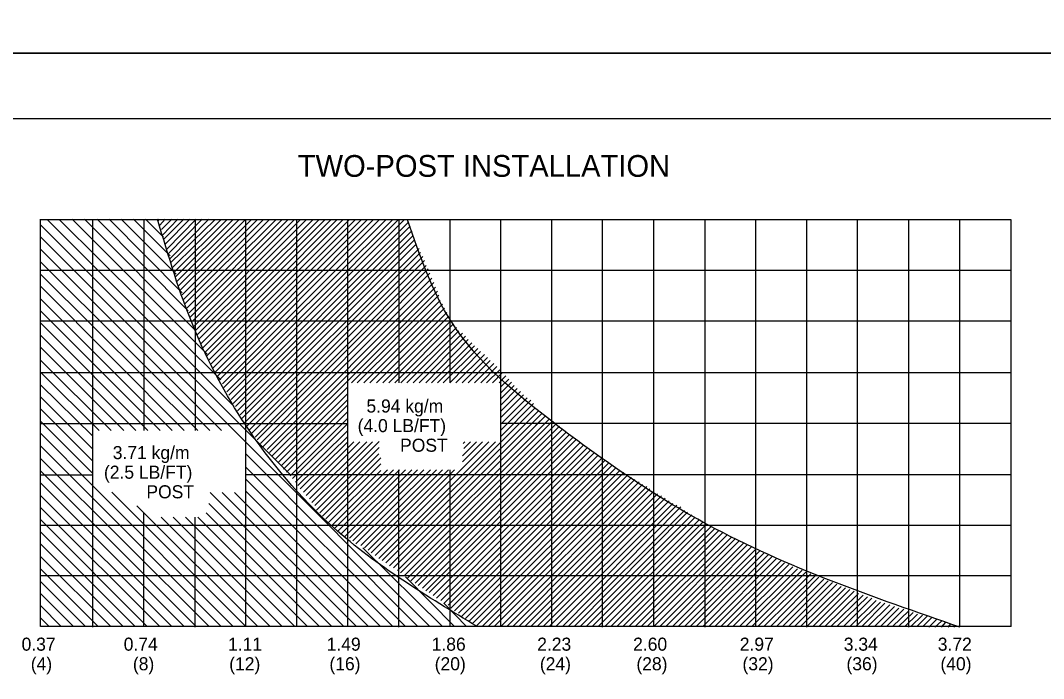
# Model space of a CAD drawing. Extents: x 644358 to 648627, y 294594 to 295782.
# Drawn here: x 645519 to 645753.8, y 295044.1 to 295195.1 of the extents above; entities that cross this region are included whole.
import ezdxf

# ---------------------------------------------------------------- set-up
doc = ezdxf.new("R2010")
doc.units = 0
for name, color, linetype in [('1', 7, 'Continuous'), ('10', 7, 'Continuous'), ('2', 7, 'Continuous'), ('4', 7, 'Continuous'), ('PLT-BNDY', 7, 'Continuous')]:
    doc.layers.add(name, color=color, linetype=linetype)

msp = doc.modelspace()

# ---------------------------------------------------------------- linework, layer by layer
at = {"layer": '1'}
msp.add_line((645239.31, 295172.63), (646025.31, 295172.63), dxfattribs=at)
at = {"layer": '10'}
for p, q in [((645567.96, 295106.63), (645525.21, 295149.38)), ((645564.96, 295112.63), (645527.96, 295149.38)), ((645561.84, 295118.5), (645530.84, 295149.5)), ((645558.84, 295124.25), (645533.71, 295149.5)), ((645557.46, 295128.5), (645536.59, 295149.5)), ((645556.09, 295132.63), (645539.34, 295149.5)), ((645554.71, 295136.88), (645542.09, 295149.5)), ((645553.34, 295141.13), (645544.96, 295149.5)), ((645551.84, 295145.38), (645547.71, 295149.5)), ((645550.59, 295149.13), (645550.84, 295149.5)), ((645550.96, 295148.13), (645552.21, 295149.5)), ((645551.34, 295147.13), (645553.71, 295149.5)), ((645551.59, 295145.88), (645555.09, 295149.5)), ((645551.84, 295144.88), (645556.46, 295149.5)), ((645552.21, 295143.75), (645557.84, 295149.5)), ((645552.59, 295142.63), (645559.34, 295149.5)), ((645552.96, 295141.63), (645560.71, 295149.5)), ((645553.34, 295140.5), (645562.21, 295149.5)), ((645553.46, 295139.5), (645563.59, 295149.38)), ((645553.84, 295138.38), (645564.96, 295149.38)), ((645554.21, 295137.25), (645566.34, 295149.38)), ((645554.59, 295136.25), (645567.71, 295149.38)), ((645554.84, 295135.13), (645569.09, 295149.38)), ((645555.21, 295134.13), (645570.59, 295149.38)), ((645555.59, 295133.13), (645571.96, 295149.38)), ((645556.09, 295132.13), (645573.34, 295149.38)), ((645556.34, 295131), (645574.71, 295149.38)), ((645556.84, 295130.13), (645576.09, 295149.38)), ((645557.21, 295129.13), (645577.59, 295149.38)), ((645557.71, 295128), (645578.96, 295149.38)), ((645557.96, 295127), (645580.34, 295149.38)), ((645558.46, 295126.13), (645581.84, 295149.38)), ((645558.84, 295125), (645583.21, 295149.38)), ((645559.21, 295124), (645584.59, 295149.38)), ((645559.59, 295123), (645586.09, 295149.38)), ((645559.96, 295122), (645587.46, 295149.38)), ((645560.46, 295121), (645588.84, 295149.38)), ((645560.84, 295120), (645590.21, 295149.38)), ((645561.21, 295118.88), (645591.59, 295149.38)), ((645561.59, 295118), (645592.96, 295149.38)), ((645562.21, 295117.13), (645594.46, 295149.38)), ((645562.59, 295116.13), (645595.84, 295149.38)), ((645563.21, 295115.38), (645597.21, 295149.38)), ((645563.71, 295114.38), (645598.59, 295149.38)), ((645564.21, 295113.5), (645599.96, 295149.38)), ((645564.71, 295112.63), (645601.34, 295149.38)), ((645565.34, 295111.75), (645602.84, 295149.38)), ((645565.71, 295110.88), (645604.34, 295149.38)), ((645566.34, 295109.88), (645605.71, 295149.38)), ((645566.84, 295109.13), (645607.09, 295149.38)), ((645567.34, 295108.13), (645608.09, 295148.88)), ((645580.96, 295090.88), (645523.59, 295148.25)), ((645567.84, 295107.25), (645608.46, 295147.88)), ((645568.34, 295106.5), (645608.84, 295146.88)), ((645570.71, 295098.31), (645523.59, 295145.5)), ((645568.84, 295105.5), (645609.09, 295145.75)), ((645569.46, 295104.63), (645609.46, 295144.75)), ((645569.84, 295103.75), (645609.84, 295143.75)), ((645565.11, 295100.99), (645523.59, 295142.63)), ((645570.46, 295102.88), (645610.51, 295142.8)), ((645570.96, 295102), (645610.81, 295141.85)), ((645562.46, 295100.99), (645523.59, 295139.75)), ((645571.46, 295101.13), (645611.33, 295140.99)), ((645572.09, 295100.38), (645611.71, 295140)), ((645572.84, 295099.5), (645612.13, 295138.92)), ((645559.7, 295100.99), (645523.59, 295136.88)), ((645573.34, 295098.88), (645612.56, 295138.1)), ((645574.09, 295098), (645612.97, 295137.14)), ((645574.59, 295097.25), (645613.42, 295135.96)), ((645575.6, 295096.64), (645613.83, 295135)), ((645556.6, 295100.99), (645523.59, 295134.13)), ((645594.09, 295113.82), (645614.25, 295133.91)), ((645594.09, 295112.44), (645614.72, 295133)), ((645594.98, 295111.96), (645615.03, 295132.08)), ((645553.85, 295100.99), (645523.59, 295131.25)), ((645596.3, 295111.96), (645615.34, 295130.88)), ((645597.79, 295111.96), (645615.84, 295130)), ((645551.1, 295100.99), (645523.59, 295128.5)), ((645599.17, 295111.96), (645616.34, 295129.13)), ((645600.67, 295111.96), (645616.84, 295128.13)), ((645602.15, 295111.96), (645617.34, 295127.25)), ((645548.23, 295100.99), (645523.59, 295125.75)), ((645603.54, 295111.96), (645617.84, 295126.25)), ((645604.9, 295111.96), (645618.34, 295125.5)), ((645545.47, 295100.99), (645523.59, 295122.88)), ((645606.31, 295111.96), (645619.09, 295124.63)), ((645607.67, 295111.96), (645619.59, 295123.88)), ((645609.15, 295111.96), (645620.43, 295123.35)), ((645610.52, 295111.96), (645621.09, 295122.64)), ((645612, 295111.96), (645621.72, 295121.89)), ((645613.32, 295111.96), (645622.6, 295121.13)), ((645614.67, 295111.96), (645623.19, 295120.48)), ((645542.72, 295100.99), (645523.59, 295120.13)), ((645616.04, 295111.96), (645623.93, 295119.85)), ((645617.51, 295111.96), (645624.59, 295119.14)), ((645618.92, 295111.96), (645625.45, 295118.49)), ((645539.83, 295100.99), (645523.59, 295117.13)), ((645620.33, 295111.96), (645626.21, 295117.74)), ((645621.75, 295111.96), (645626.79, 295117.1)), ((645623.17, 295111.96), (645627.61, 295116.4)), ((645624.61, 295111.96), (645628.28, 295115.72)), ((645537.08, 295100.99), (645523.59, 295114.38)), ((645576.17, 295095.96), (645594.09, 295113.82)), ((645625.98, 295111.96), (645629.03, 295114.92)), ((645627.35, 295111.96), (645629.63, 295114.32)), ((645628.83, 295111.96), (645630.35, 295113.54)), ((645535.59, 295099.71), (645523.59, 295111.5)), ((645576.8, 295095.22), (645594.09, 295112.44)), ((645577.52, 295094.44), (645594.09, 295111.06)), ((645629.21, 295111.05), (645631.04, 295112.8)), ((645629.21, 295109.63), (645631.71, 295112.13)), ((645629.21, 295108.25), (645632.32, 295111.35)), ((645535.59, 295096.75), (645523.59, 295108.75)), ((645578.05, 295093.58), (645594.09, 295109.48)), ((645629.21, 295106.83), (645633.02, 295110.64)), ((645629.21, 295105.42), (645633.73, 295109.94)), ((645629.21, 295104), (645634.44, 295109.23)), ((645629.21, 295102.5), (645635.24, 295108.53)), ((645578.85, 295092.89), (645594.09, 295108.13)), ((645579.39, 295092.18), (645594.09, 295106.88)), ((645602, 295071.17), (645637.02, 295106.18)), ((645629.21, 295101.13), (645636.1, 295108.01)), ((645629.21, 295099.63), (645636.76, 295107.18)), ((645535.59, 295094), (645523.59, 295106)), ((645580.08, 295091.49), (645594.09, 295105.36)), ((645580.86, 295090.65), (645594.09, 295103.88)), ((645602.86, 295070.65), (645637.86, 295105.52)), ((645603.69, 295069.98), (645638.63, 295104.92)), ((645604.57, 295069.49), (645639.4, 295104.31)), ((645637.21, 295104.88), (645637.84, 295105.5)), ((645637.21, 295102.13), (645639.46, 295104.38)), ((645637.35, 295103.64), (645638.71, 295105)), ((645535.59, 295091.13), (645523.59, 295103.13)), ((645581.43, 295089.97), (645594.09, 295102.63)), ((645605.49, 295068.9), (645640.32, 295103.61)), ((645606.2, 295068.36), (645641.02, 295103.06)), ((645607.09, 295067.63), (645641.84, 295102.5)), ((645607.85, 295067.14), (645642.71, 295102)), ((645608.62, 295066.54), (645643.46, 295101.38)), ((645637.12, 295099.18), (645641.09, 295103.13)), ((645637.21, 295100.52), (645640.34, 295103.63)), ((645535.59, 295088.34), (645523.59, 295100.38)), ((645582.1, 295089.14), (645594.09, 295101.01)), ((645582.65, 295088.43), (645594.09, 295099.67)), ((645609.54, 295065.96), (645644.21, 295100.63)), ((645610.3, 295065.47), (645644.96, 295100.13)), ((645611.25, 295064.8), (645645.84, 295099.5)), ((645535.59, 295085.5), (645523.59, 295097.5)), ((645612.96, 295056), (645570.71, 295098.31)), ((645583.22, 295087.63), (645594.09, 295098.41)), ((645583.94, 295086.86), (645595.5, 295098.41)), ((645584.57, 295086.11), (645596.87, 295098.41)), ((645585.32, 295085.36), (645598.47, 295098.41)), ((645585.84, 295084.51), (645599.75, 295098.41)), ((645586.53, 295083.82), (645601.34, 295098.5)), ((645586.96, 295082.75), (645601.34, 295097.13)), ((645600.41, 295072.32), (645626.5, 295098.41)), ((645601.24, 295071.66), (645628, 295098.41)), ((645612.02, 295064.19), (645646.59, 295099)), ((645612.81, 295063.85), (645647.46, 295098.25)), ((645613.7, 295063.12), (645648.21, 295097.63)), ((645614.47, 295062.52), (645649.09, 295097.13)), ((645620.44, 295095.23), (645623.62, 295098.41)), ((645620.44, 295093.85), (645625, 295098.41)), ((645620.59, 295098), (645620.98, 295098.41)), ((645620.71, 295096.88), (645622.25, 295098.41)), ((645562.34, 295056), (645523.59, 295094.63)), ((645610.21, 295056), (645570.71, 295095.64)), ((645587.71, 295082.13), (645601.21, 295095.63)), ((645588.34, 295081.38), (645601.68, 295094.72)), ((645615.47, 295062.02), (645649.84, 295096.5)), ((645616.16, 295061.33), (645650.71, 295096)), ((645617.13, 295060.92), (645651.46, 295095.25)), ((645617.79, 295060.21), (645652.34, 295094.63)), ((645607.34, 295056), (645570.71, 295092.63)), ((645589.09, 295080.75), (645601.68, 295093.34)), ((645590.46, 295079.25), (645603.21, 295092)), ((645591.09, 295078.5), (645604.59, 295092)), ((645591.84, 295077.88), (645605.96, 295092)), ((645592.46, 295077.13), (645607.34, 295092)), ((645593.34, 295076.63), (645608.81, 295092)), ((645594.53, 295076.32), (645610.11, 295092)), ((645595.3, 295075.71), (645611.59, 295092)), ((645595.93, 295074.97), (645613.07, 295092)), ((645597.1, 295074.64), (645614.46, 295092)), ((645597.92, 295074.09), (645615.84, 295092)), ((645598.78, 295073.57), (645617.21, 295092)), ((645599.49, 295072.91), (645618.59, 295092)), ((645618.62, 295059.66), (645653.09, 295094.13)), ((645619.52, 295059.06), (645653.96, 295093.5)), ((645620.27, 295058.44), (645654.84, 295093.13)), ((645621.1, 295057.89), (645655.71, 295092.5)), ((645559.34, 295056), (645523.59, 295091.75)), ((645604.46, 295056), (645570.71, 295089.87)), ((645589.71, 295079.88), (645601.68, 295091.84)), ((645621.97, 295057.26), (645656.59, 295091.88)), ((645622.71, 295056.75), (645657.46, 295091.38)), ((645623.71, 295056.25), (645658.34, 295090.88)), ((645624.96, 295056), (645659.21, 295090.25)), ((645626.34, 295056), (645659.96, 295089.75)), ((645556.59, 295056), (645523.59, 295089)), ((645567.84, 295056), (645535.59, 295088.34)), ((645627.71, 295056), (645660.96, 295089.25)), ((645629.21, 295056), (645661.71, 295088.63)), ((645630.59, 295056), (645662.71, 295088.13)), ((645631.96, 295056), (645663.46, 295087.63)), ((645553.71, 295056), (645523.59, 295086.13)), ((645565.09, 295056), (645534.49, 295086.6)), ((645570.71, 295056), (645539.99, 295086.83)), ((645593.21, 295056), (645562.54, 295086.8)), ((645596.09, 295056), (645565.29, 295086.8)), ((645598.84, 295056), (645568.16, 295086.8)), ((645601.59, 295056), (645570.71, 295087.11)), ((645633.34, 295056), (645664.34, 295087.13)), ((645634.71, 295056), (645665.21, 295086.5)), ((645636.09, 295056), (645666.09, 295086)), ((645637.59, 295056), (645666.96, 295085.5)), ((645550.96, 295056), (645523.59, 295083.38)), ((645573.46, 295056), (645545.71, 295083.76)), ((645590.46, 295056), (645562.21, 295084.25)), ((645638.96, 295056), (645667.84, 295084.88)), ((645640.34, 295056), (645668.71, 295084.25)), ((645641.84, 295056), (645669.59, 295083.88)), ((645643.41, 295056.01), (645670.51, 295083.48)), ((645644.71, 295056), (645671.34, 295082.63)), ((645548.09, 295056), (645523.59, 295080.63)), ((645576.34, 295056), (645551.33, 295081.12)), ((645579.09, 295056), (645554.08, 295081.12)), ((645581.96, 295056), (645556.85, 295081.12)), ((645584.84, 295056), (645559.72, 295081.12)), ((645587.59, 295056), (645561.59, 295082.12)), ((645646.09, 295056), (645672.09, 295082.25)), ((645647.46, 295056), (645673.09, 295081.63)), ((645648.84, 295056), (645673.84, 295081.13)), ((645650.21, 295056), (645674.84, 295080.63)), ((645651.59, 295056), (645675.59, 295080)), ((645653.09, 295056), (645676.46, 295079.5)), ((645654.46, 295056), (645677.46, 295079)), ((645655.84, 295056), (645678.34, 295078.5)), ((645657.21, 295056), (645679.34, 295078.13)), ((645545.34, 295056), (645523.59, 295077.75)), ((645658.59, 295056), (645680.21, 295077.63)), ((645660.09, 295056), (645681.21, 295077.13)), ((645661.46, 295056), (645682.21, 295076.63)), ((645662.84, 295056), (645683.09, 295076.25)), ((645664.34, 295056), (645683.96, 295075.75)), ((645542.59, 295056), (645523.59, 295075)), ((645615.84, 295056), (645597.56, 295074.1)), ((645665.71, 295056), (645684.96, 295075.25)), ((645667.09, 295056), (645685.84, 295074.88)), ((645668.59, 295056), (645686.84, 295074.38)), ((645669.96, 295056), (645687.84, 295073.88)), ((645671.34, 295056), (645688.71, 295073.5)), ((645539.71, 295056), (645523.59, 295072.13)), ((645672.71, 295056), (645689.71, 295073)), ((645674.09, 295056), (645690.59, 295072.5)), ((645675.59, 295056), (645691.46, 295072.13)), ((645676.96, 295056), (645692.46, 295071.63)), ((645678.34, 295056), (645693.46, 295071.13)), ((645536.84, 295056), (645523.59, 295069.25)), ((645679.71, 295056), (645694.34, 295070.63)), ((645681.09, 295056), (645695.34, 295070.25)), ((645682.46, 295056), (645696.21, 295069.75)), ((645683.96, 295056), (645697.34, 295069.25)), ((645685.34, 295056), (645698.34, 295069)), ((645686.84, 295056), (645699.21, 295068.5)), ((645533.96, 295056), (645523.59, 295066.38)), ((645618.59, 295056), (645607.38, 295067.42)), ((645688.21, 295056), (645700.34, 295068.13)), ((645689.59, 295056), (645701.34, 295067.63)), ((645691.09, 295056), (645702.21, 295067.38)), ((645692.46, 295056), (645703.34, 295066.88)), ((645693.84, 295056), (645704.34, 295066.5)), ((645695.21, 295056), (645705.34, 295066.13)), ((645696.59, 295056), (645706.34, 295065.75)), ((645697.96, 295056), (645707.34, 295065.25)), ((645699.46, 295056), (645708.34, 295064.88)), ((645700.84, 295056), (645709.34, 295064.5)), ((645702.21, 295056), (645710.34, 295064.13)), ((645531.21, 295056), (645523.59, 295063.63)), ((645703.59, 295056), (645711.34, 295063.63)), ((645704.96, 295056), (645712.34, 295063.25)), ((645706.34, 295056), (645713.34, 295062.88)), ((645707.84, 295056), (645714.34, 295062.5)), ((645709.34, 295056), (645715.34, 295062)), ((645710.71, 295056), (645716.34, 295061.63)), ((645528.34, 295056), (645523.59, 295060.88)), ((645621.34, 295056), (645616.19, 295061.36)), ((645712.09, 295056), (645717.34, 295061.38)), ((645713.46, 295056), (645718.46, 295061)), ((645714.96, 295056), (645719.59, 295060.63)), ((645716.34, 295056), (645720.59, 295060.25)), ((645717.71, 295056), (645721.71, 295060)), ((645719.09, 295056), (645722.84, 295059.63)), ((645720.46, 295056), (645723.84, 295059.25)), ((645525.59, 295056), (645523.59, 295058)), ((645721.96, 295056), (645724.84, 295058.88)), ((645723.34, 295056), (645725.96, 295058.63)), ((645724.71, 295056), (645727.09, 295058.38)), ((645726.09, 295056), (645728.09, 295058)), ((645727.46, 295055.88), (645729.21, 295057.63)), ((645728.84, 295055.88), (645730.34, 295057.25)), ((645730.34, 295055.88), (645731.34, 295057)), ((645731.84, 295055.88), (645732.46, 295056.63)), ((645733.21, 295055.88), (645733.46, 295056.25)), ((645734.59, 295055.88), (645734.59, 295055.88))]:
    msp.add_line(p, q, dxfattribs=at)
at = {"layer": '2'}
for p, q in [((645523.59, 295056), (645523.59, 295149.5)), ((645746.34, 295149.38), (645523.59, 295149.38)), ((645535.59, 295090.88), (645535.59, 295149.38)), ((645547.34, 295149.38), (645547.34, 295100.99)), ((645559.09, 295149.38), (645559.09, 295100.99)), ((645570.71, 295090.88), (645570.71, 295149.38)), ((645582.46, 295056), (645582.46, 295149.38)), ((645594.09, 295102.63), (645594.09, 295149.38)), ((645605.84, 295149.38), (645605.84, 295111.96)), ((645617.59, 295111.96), (645617.59, 295149.38)), ((645629.21, 295102.63), (645629.21, 295149.38)), ((645640.96, 295056), (645640.96, 295149.38)), ((645652.59, 295055.88), (645652.59, 295149.38)), ((645664.34, 295056), (645664.34, 295149.38)), ((645676.09, 295055.88), (645676.09, 295149.38)), ((645687.71, 295056), (645687.71, 295149.38)), ((645699.46, 295055.88), (645699.46, 295149.38)), ((645711.09, 295056), (645711.09, 295149.38)), ((645722.84, 295055.88), (645722.84, 295149.38)), ((645734.59, 295056), (645734.59, 295149.38)), ((645746.34, 295056), (645746.34, 295149.38)), ((645746.34, 295137.75), (645523.59, 295137.75)), ((645746.34, 295126.13), (645523.59, 295126.13)), ((645746.34, 295114.25), (645523.59, 295114.25)), ((645523.59, 295102.63), (645594.09, 295102.63)), ((645594.09, 295056), (645594.09, 295102.63)), ((645649.96, 295102.63), (645629.21, 295102.63)), ((645629.21, 295056), (645629.21, 295102.63)), ((645746.34, 295102.63), (645649.96, 295102.63)), ((645605.84, 295055.88), (645605.84, 295092)), ((645617.59, 295056), (645617.59, 295092)), ((645523.59, 295090.88), (645535.59, 295090.88)), ((645535.59, 295055.88), (645535.59, 295090.88)), ((645570.71, 295056), (645570.71, 295090.88)), ((645593.46, 295090.88), (645570.71, 295090.88)), ((645746.34, 295090.88), (645593.46, 295090.88)), ((645547.34, 295056), (645547.34, 295082.13)), ((645559.09, 295055.88), (645559.09, 295081.12)), ((645746.34, 295079.25), (645523.59, 295079.25)), ((645746.34, 295067.63), (645523.59, 295067.63)), ((645746.34, 295056), (645523.59, 295056))]:
    msp.add_line(p, q, dxfattribs=at)
at = {"layer": '4'}
for points in [[(645623.84, 295056), (645590.84, 295078.75), (645570.71, 295102.25), (645558.84, 295124.5), (645550.46, 295149.5)], [(645734.59, 295055.88), (645676.71, 295079.38), (645641.59, 295102.63), (645617.96, 295125.88), (645607.84, 295149.38)]]:
    msp.add_spline(points, degree=3, dxfattribs=at)
at = {"layer": 'PLT-BNDY'}
for points in [[(645199.31, 295781.63), (646040.31, 295781.63), (646040.31, 295187.63), (645199.31, 295187.63)], [(645199.31, 295187.63), (646040.31, 295187.63), (646040.31, 294593.63), (645199.31, 294593.63)]]:
    msp.add_lwpolyline(points, close=True, dxfattribs=at)

# ---------------------------------------------------------------- texts
at = {"layer": '2'}
msp.add_text('TWO-POST INSTALLATION', height=5, dxfattribs=at).set_placement((645582.64, 295159.24))
at = {"layer": '4'}
for s, p in [('5.94 kg/m', (645598.4, 295105.14)), ('(4.0 LB/FT)', (645596.38, 295100.64)), ('POST', (645606.12, 295096.14)), ('3.71 kg/m', (645540.19, 295094.45)), ('(2.5 LB/FT)', (645538.17, 295089.95)), ('POST', (645547.91, 295085.45)), ('0.37', (645519.27, 295050.48)), ('0.74', (645542.7, 295050.48)), ('1.11', (645566.64, 295050.48)), ('1.49', (645589.27, 295050.48)), ('1.86', (645613.36, 295050.48)), ('2.23', (645637.58, 295050.48)), ('2.60', (645659.59, 295050.48)), ('2.97', (645684.06, 295050.48)), ('3.34', (645707.92, 295050.48)), ('3.72', (645729.49, 295050.48)), ('(4)', (645521.38, 295045.98)), ('(8)', (645544.81, 295045.98)), ('(12)', (645566.91, 295045.98)), ('(16)', (645589.9, 295045.98)), ('(20)', (645614.06, 295045.98)), ('(24)', (645638.19, 295045.98)), ('(28)', (645660.34, 295045.98)), ('(32)', (645684.68, 295045.98)), ('(36)', (645708.54, 295045.98)), ('(40)', (645730.1, 295045.98))]:
    msp.add_text(s, height=3, dxfattribs=at).set_placement(p)

doc.saveas('drawing.dxf')
